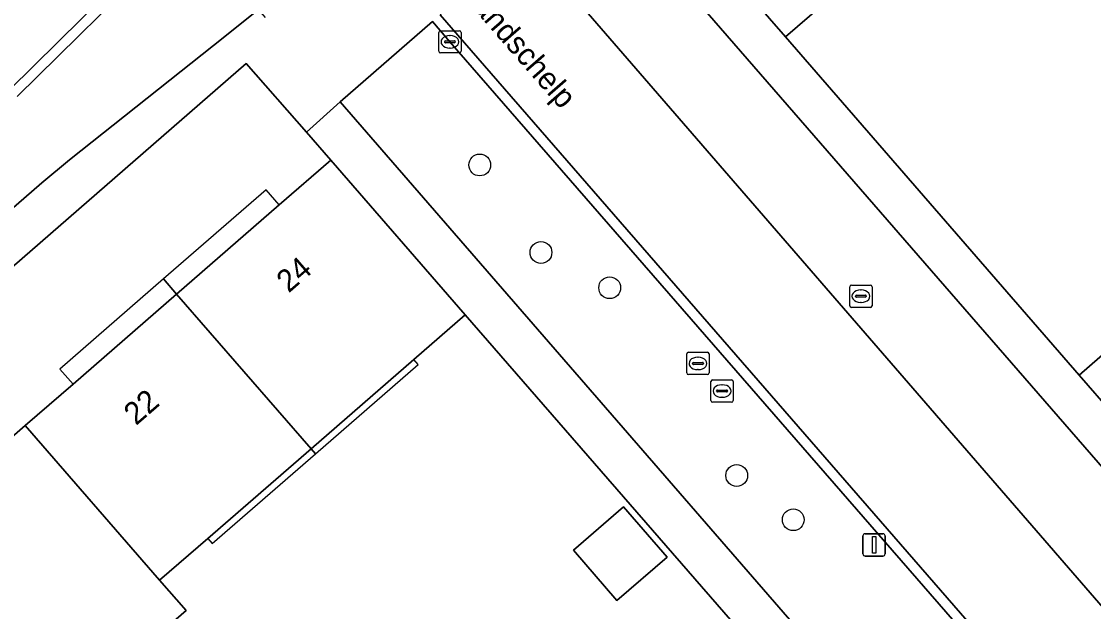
# Model space of a CAD drawing. Extents: x 155887 to 156869, y 383880 to 384678.
# Drawn here: x 156405.9 to 156453.99, y 384357.42 to 384383.91 of the extents above; entities that cross this region are included whole.
import ezdxf

# ---------------------------------------------------------------- set-up
doc = ezdxf.new("R2010")
doc.units = 0
for name, color, linetype in [('IMGEO_Berm_groen', 7, 'Continuous'), ('IMGEO_Boom', 7, 'Continuous'), ('IMGEO_Erf', 7, 'Continuous'), ('IMGEO_Greppel_droge_sloot', 7, 'Continuous'), ('IMGEO_Kolk', 7, 'Continuous'), ('IMGEO_Lichtmast', 7, 'Continuous'), ('IMGEO_Muur', 7, 'Continuous'), ('IMGEO_Openbare_ruimte_label', 7, 'Continuous'), ('IMGEO_Pand', 7, 'Continuous'), ('IMGEO_Pand_nummerreeks', 7, 'Continuous'), ('IMGEO_Pand_overbouw', 7, 'Continuous'), ('IMGEO_Parkeervlak_open', 7, 'Continuous'), ('IMGEO_Rijbaan_lokaal_gesloten', 7, 'Continuous'), ('IMGEO_Rijbaan_lokaal_open', 7, 'Continuous'), ('IMGEO_Rioolput', 7, 'Continuous'), ('IMGEO_Voetpad_open', 7, 'Continuous')]:
    doc.layers.add(name, color=color, linetype=linetype)

msp = doc.modelspace()

# ---------------------------------------------------------------- linework, layer by layer
at = {"layer": 'IMGEO_Berm_groen'}
for points in [[(156425.117, 384382.992), (156424.328, 384383.909), (156420.201, 384380.296), (156451.581, 384344.121), (156452.282, 384343.313)], [(156452.194, 384351.834), (156451.073, 384353.142), (156425.117, 384382.992)]]:
    msp.add_lwpolyline(points, dxfattribs=at)
at = {"layer": 'IMGEO_Boom'}
for centre in [(156426.455, 384377.466), (156429.201, 384373.541), (156432.283, 384371.957), (156437.981, 384363.53), (156440.518, 384361.545)]:
    msp.add_circle(centre, 0.489, dxfattribs=at)
at = {"layer": 'IMGEO_Erf'}
for points in [[(156455.989, 384396.971), (156453.963, 384395.21), (156455.997, 384392.871), (156449.209, 384386.97), (156447.371, 384389.083), (156447.175, 384389.309), (156442.427, 384385.183), (156440.17, 384383.221), (156453.343, 384368.04), (156455.661, 384370.054)], [(156401.578, 384320.396), (156406.224, 384324.434), (156410.625, 384328.259), (156413.013, 384330.335), (156415.132, 384332.177), (156419.802, 384336.236), (156424.325, 384340.167), (156426.593, 384342.138), (156428.735, 384344), (156433.382, 384348.039), (156437.846, 384351.919), (156440.305, 384354.056), (156425.805, 384370.742), (156423.497, 384368.737), (156418.886, 384364.732), (156414.256, 384360.709), (156412.095, 384358.832), (156413.279, 384357.469), (156409.012, 384353.762), (156410.882, 384351.61), (156408.356, 384349.417), (156405.5, 384352.705)]]:
    msp.add_lwpolyline(points, dxfattribs=at)
for points in [[(156403.859, 384363.856), (156406.066, 384365.774), (156408.21, 384367.636), (156412.858, 384371.674), (156417.461, 384375.672), (156419.78, 384377.687), (156418.678, 384378.941), (156415.972, 384382.017), (156374.96, 384346.313), (156378.699, 384341.999), (156381.032, 384344.026), (156385.694, 384348.075), (156390.266, 384352.047), (156392.485, 384353.975), (156394.62, 384355.83), (156399.275, 384359.874)], [(156432.611, 384357.923), (156430.658, 384360.172), (156432.902, 384362.121), (156434.856, 384359.872)]]:
    msp.add_lwpolyline(points, close=True, dxfattribs=at)
at = {"layer": 'IMGEO_Greppel_droge_sloot'}
msp.add_lwpolyline([(156431.574, 384390.156), (156428.512, 384387.527), (156454.804, 384357.143), (156455.52, 384356.291), (156458.679, 384358.946)], close=True, dxfattribs=at)
at = {"layer": 'IMGEO_Kolk'}
for p, q in [((156424.617, 384382.567), (156424.617, 384383.419)), ((156424.692, 384383.493), (156425.544, 384383.493)), ((156425.618, 384383.419), (156425.618, 384382.567)), ((156424.876, 384382.987), (156424.876, 384382.999)), ((156425.314, 384382.95), (156424.916, 384382.95)), ((156424.919, 384383.036), (156425.317, 384383.036)), ((156425.105, 384383.273), (156425.13, 384383.273)), ((156425.36, 384382.999), (156425.36, 384382.987)), ((156425.544, 384382.493), (156424.692, 384382.493)), ((156425.128, 384382.713), (156425.103, 384382.713)), ((156443.052, 384371.15), (156443.052, 384372.002)), ((156443.127, 384372.076), (156443.979, 384372.076)), ((156444.053, 384372.002), (156444.053, 384371.15)), ((156443.311, 384371.57), (156443.311, 384371.582)), ((156443.749, 384371.533), (156443.351, 384371.533)), ((156443.354, 384371.619), (156443.752, 384371.619)), ((156443.54, 384371.856), (156443.565, 384371.856)), ((156443.795, 384371.582), (156443.795, 384371.57)), ((156443.979, 384371.076), (156443.127, 384371.076)), ((156443.563, 384371.296), (156443.538, 384371.296))]:
    msp.add_line(p, q, dxfattribs=at)
for points in [[(156424.617, 384382.567), (156424.617, 384383.419)], [(156424.692, 384383.493), (156425.544, 384383.493)], [(156425.618, 384383.419), (156425.618, 384382.567)], [(156425.544, 384382.493), (156424.692, 384382.493)], [(156443.052, 384371.15), (156443.052, 384372.002)], [(156443.127, 384372.076), (156443.979, 384372.076)], [(156444.053, 384372.002), (156444.053, 384371.15)], [(156443.979, 384371.076), (156443.127, 384371.076)]]:
    msp.add_lwpolyline(points, dxfattribs=at)
for centre, radius, start, end in [((156424.694, 384383.417), 0.0765, 91.552, 178.448), ((156424.694, 384383.417), 0.0765, 91.552, 178.448), ((156425.542, 384383.417), 0.0765, 1.552, 88.448), ((156425.542, 384383.417), 0.0765, 1.552, 88.448), ((156424.916, 384382.996), 0.0403, 85.8775, 175.7526), ((156424.913, 384382.986), 0.0366, 178.938, 274.7102), ((156425.317, 384382.993), 0.043, 264.8664, 352.4533), ((156425.321, 384382.998), 0.0386, 1.7309, 96.639), ((156424.694, 384382.569), 0.0765, 181.552, 268.448), ((156424.694, 384382.569), 0.0765, 181.552, 268.448), ((156425.542, 384382.569), 0.0765, 271.552, 358.448), ((156425.542, 384382.569), 0.0765, 271.552, 358.448), ((156443.129, 384372), 0.0765, 91.552, 178.448), ((156443.129, 384372), 0.0765, 91.552, 178.448), ((156443.977, 384372), 0.0765, 1.552, 88.448), ((156443.977, 384372), 0.0765, 1.552, 88.448), ((156443.351, 384371.579), 0.0403, 85.8775, 175.7526), ((156443.348, 384371.569), 0.0366, 178.938, 274.7102), ((156443.752, 384371.576), 0.043, 264.8664, 352.4533), ((156443.756, 384371.581), 0.0386, 1.7309, 96.639), ((156443.129, 384371.152), 0.0765, 181.552, 268.448), ((156443.129, 384371.152), 0.0765, 181.552, 268.448), ((156443.977, 384371.152), 0.0765, 271.552, 358.448), ((156443.977, 384371.152), 0.0765, 271.552, 358.448)]:
    msp.add_arc(centre, radius, start, end, dxfattribs=at)
for centre, major_axis, ratio, start_param, end_param in [((156425.104, 384382.993), (-0.387, 0.002), 0.722429, 4.712389, 7.853982), ((156425.129, 384382.993), (-0.39, 0.002), 0.717154, 1.570796, 4.712389), ((156443.539, 384371.576), (-0.387, 0.002), 0.722429, 4.712389, 7.853982), ((156443.564, 384371.576), (-0.39, 0.002), 0.717154, 1.570796, 4.712389)]:
    msp.add_ellipse(centre, major_axis=major_axis, ratio=ratio, start_param=start_param, end_param=end_param, dxfattribs=at)
at = {"layer": 'IMGEO_Lichtmast'}
for p, q in [((156443.646, 384360.016), (156443.646, 384360.816)), ((156443.646, 384360.816), (156443.646, 384360.016)), ((156443.746, 384360.916), (156444.536, 384360.916)), ((156444.536, 384360.916), (156443.746, 384360.916)), ((156444.636, 384360.816), (156444.636, 384360.016)), ((156444.636, 384360.016), (156444.636, 384360.816)), ((156444.536, 384359.916), (156443.746, 384359.916)), ((156443.746, 384359.916), (156444.536, 384359.916))]:
    msp.add_line(p, q, dxfattribs=at)
msp.add_lwpolyline([(156444.066, 384360.791), (156444.216, 384360.791), (156444.216, 384360.041), (156444.066, 384360.041), (156444.066, 384360.791)], dxfattribs=at)
for centre, start, end in [((156443.746, 384360.816), 90, 180), ((156443.746, 384360.816), 90, 180), ((156444.536, 384360.816), 0, 90), ((156444.536, 384360.816), 360, 90), ((156443.746, 384360.016), 180, 270), ((156443.746, 384360.016), 180, 270), ((156444.536, 384360.016), 270, 0), ((156444.536, 384360.016), 270, 0)]:
    msp.add_arc(centre, 0.1, start, end, dxfattribs=at)
at = {"layer": 'IMGEO_Muur'}
for points in [[(156440.17, 384383.221), (156453.343, 384368.04)], [(156425.805, 384370.742), (156440.305, 384354.056)]]:
    msp.add_lwpolyline(points, dxfattribs=at)
at = {"layer": 'IMGEO_Pand'}
for points in [[(156441.125, 384396.241), (156436.468, 384392.193), (156434.135, 384390.165), (156440.17, 384383.221), (156442.427, 384385.183), (156447.175, 384389.309)], [(156418.886, 384364.732), (156423.497, 384368.737), (156425.805, 384370.742), (156419.78, 384377.687), (156417.461, 384375.672), (156412.858, 384371.674)], [(156460.342, 384374.12), (156455.661, 384370.054), (156453.343, 384368.04), (156459.376, 384361.094), (156461.701, 384363.114), (156466.373, 384367.172)], [(156412.095, 384358.832), (156414.256, 384360.709), (156418.886, 384364.732), (156412.858, 384371.674), (156408.21, 384367.636), (156406.066, 384365.774)], [(156412.095, 384358.832), (156406.066, 384365.774), (156403.859, 384363.856), (156399.275, 384359.874), (156405.303, 384352.932), (156405.5, 384352.705), (156408.356, 384349.417), (156410.882, 384351.61), (156409.012, 384353.762), (156413.279, 384357.469)], [(156432.611, 384357.923), (156434.856, 384359.872), (156432.902, 384362.121), (156430.658, 384360.172)]]:
    msp.add_lwpolyline(points, close=True, dxfattribs=at)
at = {"layer": 'IMGEO_Pand_overbouw'}
for points in [[(156412.858, 384371.674), (156417.461, 384375.672), (156416.868, 384376.353), (156412.27, 384372.351)], [(156408.21, 384367.636), (156412.858, 384371.674), (156412.27, 384372.351), (156407.624, 384368.307)], [(156423.497, 384368.737), (156418.886, 384364.732), (156419.083, 384364.505), (156423.694, 384368.511)], [(156414.256, 384360.709), (156414.453, 384360.483), (156419.083, 384364.505), (156418.886, 384364.732)]]:
    msp.add_lwpolyline(points, close=True, dxfattribs=at)
at = {"layer": 'IMGEO_Parkeervlak_open'}
msp.add_lwpolyline([(156404.195, 384379.701), (156405.36, 384380.844), (156411.86, 384387.27), (156409.376, 384390.196), (156359.824, 384347.104), (156341.025, 384330.814), (156343.939, 384327.348), (156344.972, 384328.151), (156363.415, 384344.239)], close=True, dxfattribs=at)
at = {"layer": 'IMGEO_Rijbaan_lokaal_gesloten'}
msp.add_lwpolyline([(156428.512, 384387.527), (156424.676, 384384.21), (156425.465, 384383.293), (156451.421, 384353.443), (156455.52, 384356.291), (156454.804, 384357.143)], close=True, dxfattribs=at)
for points in [[(156412.146, 384386.905), (156405.699, 384380.533)], [(156382.065, 384355.135), (156406.806, 384376.665), (156408.048, 384377.704), (156415.015, 384383.239), (156416.533, 384384.445)]]:
    msp.add_lwpolyline(points, dxfattribs=at)
at = {"layer": 'IMGEO_Rijbaan_lokaal_open'}
for points in [[(156405.699, 384380.533), (156412.146, 384386.905), (156412.175, 384386.934), (156412.379, 384387.115), (156413.42, 384388.121), (156414.064, 384388.839), (156414.387, 384389.26), (156414.671, 384389.709), (156414.914, 384390.181), (156415.113, 384390.673), (156415.268, 384391.18), (156415.377, 384391.7), (156415.439, 384392.227), (156415.453, 384392.758), (156415.42, 384393.288), (156415.34, 384393.813), (156415.213, 384394.328), (156415.04, 384394.83), (156414.98, 384394.994)], [(156413.481, 384388.877), (156413.09, 384388.441), (156412.066, 384387.453), (156411.86, 384387.27), (156405.36, 384380.844)], [(156424.328, 384383.909), (156425.117, 384382.992), (156451.073, 384353.142), (156452.194, 384351.834)], [(156451.421, 384353.443), (156425.465, 384383.293), (156424.676, 384384.21)]]:
    msp.add_lwpolyline(points, dxfattribs=at)
at = {"layer": 'IMGEO_Rioolput'}
for p, q in [((156435.743, 384368.134), (156435.743, 384368.986)), ((156435.818, 384369.06), (156436.67, 384369.06)), ((156436.744, 384368.986), (156436.744, 384368.134)), ((156436.002, 384368.554), (156436.002, 384368.566)), ((156436.44, 384368.517), (156436.042, 384368.517)), ((156436.045, 384368.603), (156436.443, 384368.603)), ((156436.231, 384368.84), (156436.256, 384368.84)), ((156436.486, 384368.566), (156436.486, 384368.554)), ((156436.67, 384368.06), (156435.818, 384368.06)), ((156436.254, 384368.28), (156436.229, 384368.28)), ((156436.823, 384366.895), (156436.823, 384367.747)), ((156436.898, 384367.821), (156437.75, 384367.821)), ((156437.311, 384367.601), (156437.336, 384367.601)), ((156437.824, 384367.747), (156437.824, 384366.895)), ((156437.082, 384367.315), (156437.082, 384367.327)), ((156437.52, 384367.278), (156437.122, 384367.278)), ((156437.125, 384367.364), (156437.523, 384367.364)), ((156437.566, 384367.327), (156437.566, 384367.315)), ((156437.75, 384366.821), (156436.898, 384366.821)), ((156437.334, 384367.041), (156437.309, 384367.041))]:
    msp.add_line(p, q, dxfattribs=at)
for points in [[(156435.743, 384368.134), (156435.743, 384368.986)], [(156435.818, 384369.06), (156436.67, 384369.06)], [(156436.744, 384368.986), (156436.744, 384368.134)], [(156436.67, 384368.06), (156435.818, 384368.06)], [(156436.823, 384366.895), (156436.823, 384367.747)], [(156436.898, 384367.821), (156437.75, 384367.821)], [(156437.824, 384367.747), (156437.824, 384366.895)], [(156437.75, 384366.821), (156436.898, 384366.821)]]:
    msp.add_lwpolyline(points, dxfattribs=at)
for centre, radius, start, end in [((156435.82, 384368.984), 0.0765, 91.552, 178.448), ((156435.82, 384368.984), 0.0765, 91.552, 178.448), ((156436.668, 384368.984), 0.0765, 1.552, 88.448), ((156436.668, 384368.984), 0.0765, 1.552, 88.448), ((156436.042, 384368.563), 0.0403, 85.8775, 175.7526), ((156436.039, 384368.553), 0.0366, 178.938, 274.7102), ((156436.443, 384368.56), 0.043, 264.8664, 352.4533), ((156436.447, 384368.565), 0.0386, 1.7309, 96.639), ((156435.82, 384368.136), 0.0765, 181.552, 268.448), ((156435.82, 384368.136), 0.0765, 181.552, 268.448), ((156436.668, 384368.136), 0.0765, 271.552, 358.448), ((156436.668, 384368.136), 0.0765, 271.552, 358.448), ((156436.9, 384367.745), 0.0765, 91.552, 178.448), ((156436.9, 384367.745), 0.0765, 91.552, 178.448), ((156437.748, 384367.745), 0.0765, 1.552, 88.448), ((156437.748, 384367.745), 0.0765, 1.552, 88.448), ((156437.122, 384367.324), 0.0403, 85.8775, 175.7526), ((156437.119, 384367.314), 0.0366, 178.938, 274.7102), ((156437.523, 384367.321), 0.043, 264.8664, 352.4533), ((156437.527, 384367.326), 0.0386, 1.7309, 96.639), ((156436.9, 384366.897), 0.0765, 181.552, 268.448), ((156436.9, 384366.897), 0.0765, 181.552, 268.448), ((156437.748, 384366.897), 0.0765, 271.552, 358.448), ((156437.748, 384366.897), 0.0765, 271.552, 358.448)]:
    msp.add_arc(centre, radius, start, end, dxfattribs=at)
for centre, major_axis, ratio, start_param, end_param in [((156436.23, 384368.56), (-0.387, 0.002), 0.722429, 4.712389, 7.853982), ((156436.255, 384368.56), (-0.39, 0.002), 0.717154, 1.570796, 4.712389), ((156437.31, 384367.321), (-0.387, 0.002), 0.722429, 4.712389, 7.853982), ((156437.335, 384367.321), (-0.39, 0.002), 0.717154, 1.570796, 4.712389)]:
    msp.add_ellipse(centre, major_axis=major_axis, ratio=ratio, start_param=start_param, end_param=end_param, dxfattribs=at)
at = {"layer": 'IMGEO_Voetpad_open'}
for points in [[(156440.17, 384383.221), (156434.135, 384390.165), (156433.074, 384391.385), (156431.574, 384390.156), (156458.679, 384358.946), (156461.655, 384355.519), (156463.122, 384356.762), (156459.376, 384361.094), (156453.343, 384368.04)], [(156420.201, 384380.296), (156418.678, 384378.941), (156419.78, 384377.687), (156425.805, 384370.742), (156440.305, 384354.056), (156446.34, 384347.112), (156450.097, 384342.754), (156451.581, 384344.121)]]:
    msp.add_lwpolyline(points, close=True, dxfattribs=at)
for points in [[(156416.84, 384384.082), (156416.533, 384384.445), (156415.015, 384383.239), (156408.048, 384377.704), (156406.806, 384376.665), (156382.065, 384355.135), (156380.743, 384353.938), (156374.028, 384347.338), (156374.339, 384347.004), (156374.96, 384346.313), (156415.972, 384382.017)], [(156415.972, 384382.017), (156418.678, 384378.941), (156420.201, 384380.296), (156424.328, 384383.909)]]:
    msp.add_lwpolyline(points, dxfattribs=at)

# ---------------------------------------------------------------- texts
at = {"layer": 'IMGEO_Openbare_ruimte_label'}
msp.add_text('Zandschelp', height=1, rotation=310.9865, dxfattribs=at).set_placement((156425.578, 384385.143))
at = {"layer": 'IMGEO_Pand_nummerreeks'}
for s, p in [('24', (156417.883, 384371.696)), ('22', (156411.035, 384365.746))]:
    msp.add_text(s, height=1, rotation=40.9816, dxfattribs=at).set_placement(p)

doc.saveas('drawing.dxf')
